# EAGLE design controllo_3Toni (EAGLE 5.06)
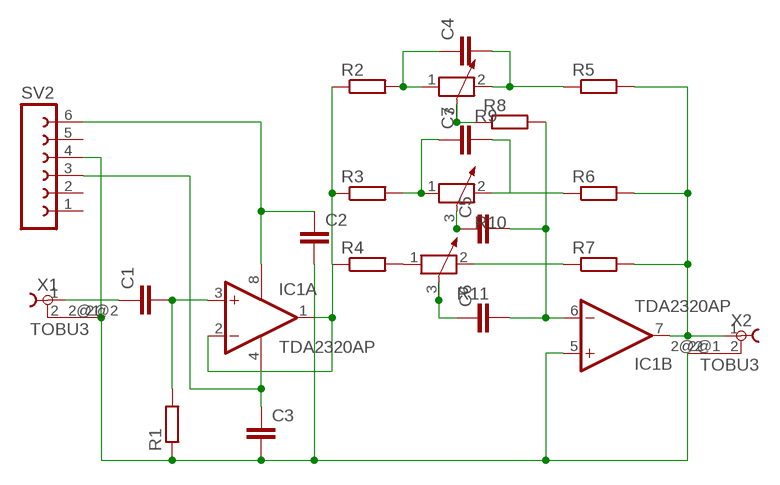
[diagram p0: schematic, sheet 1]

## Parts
C1  C-EU050-025X075  [C050-025X075]
C2  C-EU050-025X075  [C050-025X075]
C3  C-EU050-025X075  [C050-025X075]
C4  C-EU050-025X075  [C050-025X075]
C5  C-EU050-025X075  [C050-025X075]
C6  C-EU050-025X075  [C050-025X075]
C7  C-EU050-025X075  [C050-025X075]
IC1  TDA2320AP  [DIL08]
R1  R-EU_0207/10  [0207/10]
R2  R-EU_0207/10  [0207/10]
R3  R-EU_0207/10  [0207/10]
R4  R-EU_0207/10  [0207/10]
R5  R-EU_0207/10  [0207/10]
R6  R-EU_0207/10  [0207/10]
R7  R-EU_0207/10  [0207/10]
R8  R-EU_0207/10  [0207/10]
R9  POTENTIOMETER_PT-10S  [PT-10S]
R10  POTENTIOMETER_PT-10S  [PT-10S]
R11  POTENTIOMETER_PT-10S  [PT-10S]
SV2  FE06-1  [FE06]
X1  TOBU3  [TOBU3]
X2  TOBU3  [TOBU3]

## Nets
N$1: IC1.1(A:OUT) IC1.2(A:-IN) R2.1 R3.1 R4.1
N$2: C4.2 R5.1 R9.2
N$3: C7.2 R6.1 R10.2
N$4: R7.1 R11.2
N$5: C5.1 R10.3
N$6: C6.1 R11.3
N$7: C2.1 IC1.8(P:V+) SV2.6
N$8: C4.1 R2.2 R9.1
N$9: R8.1 R9.3
N$10: C5.2 C6.2 IC1.6(B:-IN) R8.2
N$11: IC1.7(B:OUT) R5.2 R6.2 R7.2 X2.1
N$12: C1.2 IC1.3(A:+IN) R1.2
N$13: C1.1 X1.1
N$14: C3.1 IC1.4(P:V-) SV2.3
N$15: C2.2 C3.2 IC1.5(B:+IN) R1.1 SV2.4 X1.2@2 X2.2@2
N$16: R4.2 R11.1
N$17: C7.1 R3.2 R10.1
Unconnected: SV2.1 SV2.2 SV2.5 X1.2 X1.2@1 X2.2 X2.2@1

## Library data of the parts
C1-C7 = resistor:C-EU: CAPACITOR, European symbol
IC1 = linear:TDA2320A: Power OP AMP
R1-R8 = resistor:R-EU_: RESISTOR, European symbol
R9-R11 = rcl:POTENTIOMETER_: Potentiometer
SV2 = con-lsta:FE06-1: FEMALE HEADER
X1 X2 = con-hirschmann:TOBU3: Female Cinch CONNECTOR ( RCA Jack )

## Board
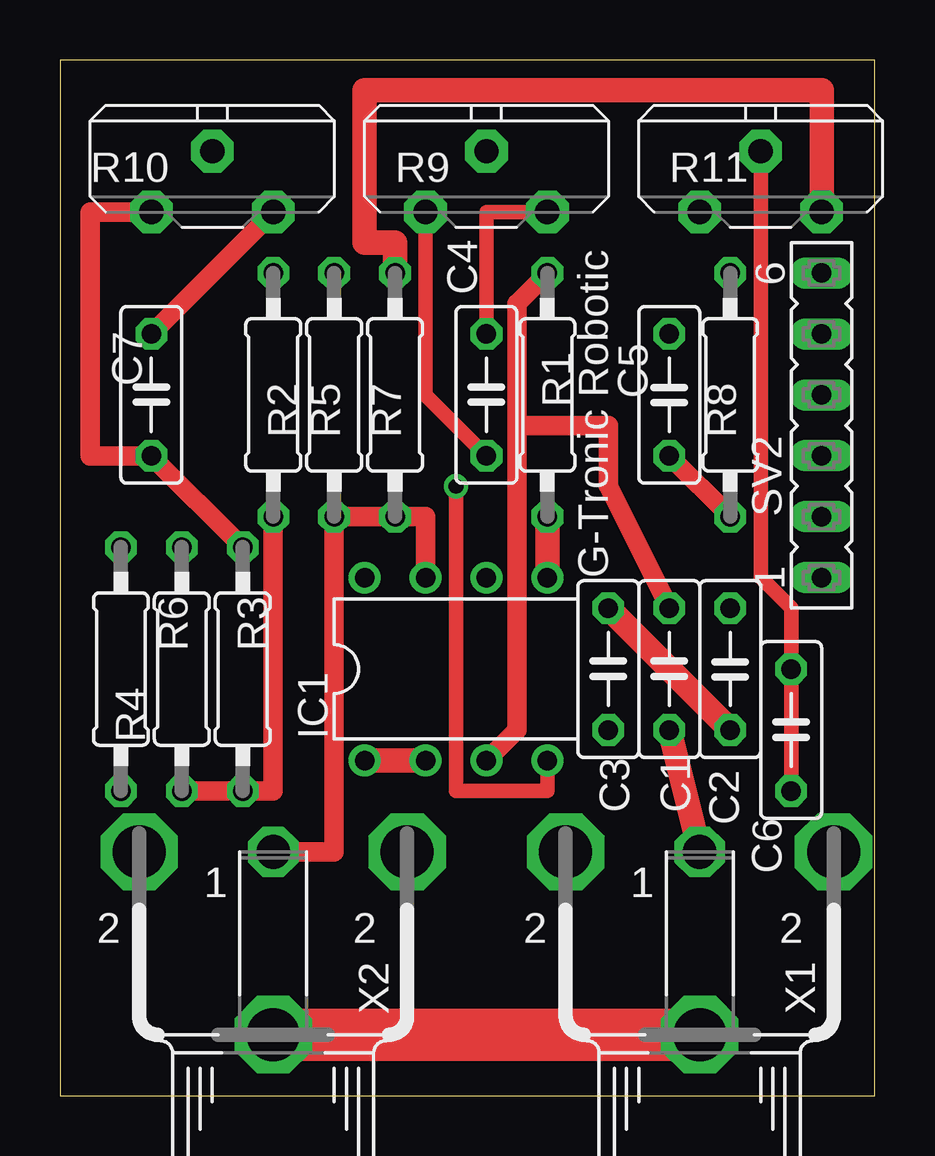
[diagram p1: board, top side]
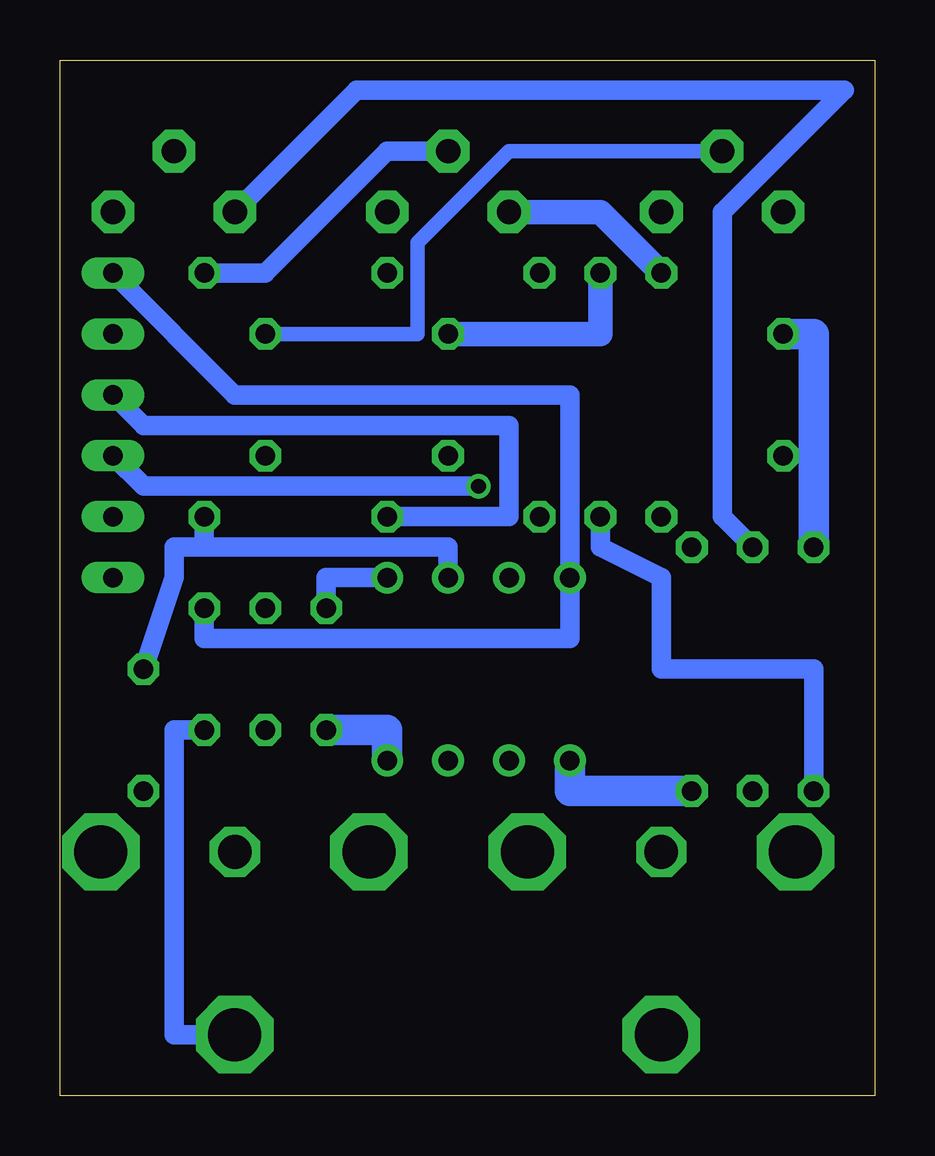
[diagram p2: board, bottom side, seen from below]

Size 33.96 x 43.17 mm. Coordinates in mm from the lower left corner, seen from the top.
Outline: 0,0 33.96,0 33.96,43.17 0,43.17 0,0
Copper layers (1*16): Top 0.035mm / dielectric 1.5mm / Bottom 0.035mm
Design rules "default": minimum track width 10mil, minimum drill 24mil, track to track 8mil, track to pad 8mil, pad to pad 8mil, via to via 8mil, smd to smd 8mil, copper to edge 40mil, drill to drill 8mil, minimum pad ring 10mil, minimum via ring 8mil, stop-mask expansion 4mil, vias tented up to drill 0mil, thermal gap 10mil

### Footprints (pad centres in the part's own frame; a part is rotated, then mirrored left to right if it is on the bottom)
C050-025X075 = drill 0.813 octagon: 1 -2.54,0; 2 2.54,0
DIL08 = drill 0.813 pad 1.27 round: 1 -3.81,-3.81; 2 -1.27,-3.81; 3 1.27,-3.81; 4 3.81,-3.81; 5 3.81,3.81; 6 1.27,3.81; 7 -1.27,3.81; 8 -3.81,3.81
0207/10 = drill 0.813 octagon: 1 -5.08,0; 2 5.08,0
PT-10S = drill 1.016 pad 1.778 octagon: 1 -2.54,-1.27; 2 2.54,-1.27; 3 0,1.27
FE06 = drill 0.813 long: 1 -6.35,0; 2 -3.81,0; 3 -1.27,0; 4 1.27,0; 5 3.81,0; 6 6.35,0
TOBU3 = drill 1.397 octagon: 1 0,-2.54 | drill 2.21 octagon: 2 5.588,-2.54; 2@1 -5.588,-2.54; 2@2 0,5.08

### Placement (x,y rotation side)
C1  25.4,17.78 90 top
C2  27.94,17.78 270 top
C3  22.86,17.78 90 top
C4  17.78,29.21 90 top
C5  25.4,29.21 270 top
C6  30.48,15.24 90 top
C7  3.81,29.21 90 top
IC1  16.51,17.78 0 top
R1  20.32,29.21 90 top
R2  8.89,29.21 90 top
R3  7.62,17.78 90 top
R4  5.08,17.78 90 top
R5  11.43,29.21 270 top
R6  2.54,17.78 270 top
R7  13.97,29.21 270 top
R8  27.94,29.21 270 top
R9  17.78,38.1 0 top
R10  6.35,38.1 0 top
R11  29.21,38.1 0 top
SV2  31.75,27.94 90 top
X1  26.67,7.62 180 top
X2  8.89,7.62 180 top

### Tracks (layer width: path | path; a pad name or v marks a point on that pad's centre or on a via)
N$1
  Top 0.813: R4.1 R3.1 8.89,12.7 R2.1
  Top 1.016: IC1.1 IC1.2
  Bottom 1.27: IC1.1 12.7,12.7 R3.1
N$2
  Top 0.61: R9.2 17.78,36.83 C4.2
  Bottom 1.016: R5.1 11.43,31.75 C4.2
N$3
  Top 0.813: C7.2 R10.2
  Bottom 1.27: R6.1 2.54,31.75 C7.2
N$4
  Top 1.016: R7.1 13.97,35.56 12.7,35.56 12.7,41.91 31.75,41.91 R11.2
N$5
  Bottom 0.61: C5.1 22.86,31.75 19.05,31.75 19.05,35.56 15.24,39.37 R10.3
N$6
  Top 0.61: C6.1 30.48,20.32 29.21,21.59 R11.3
N$7
  Bottom 0.813: C2.1 27.94,19.05 12.7,19.05 IC1.8 12.7,29.21 26.67,29.21 SV2.6
N$8
  Top 0.61: C4.1 15.24,29.21 R9.1
  Bottom 1.016: R2.2 11.43,36.83 R9.1
N$9
  Bottom 0.813: R8.1 25.4,34.29 20.32,39.37 R9.3
N$10
  Top 0.813: R8.2 C5.2
  Bottom 0.813: IC1.6 17.78,22.86 27.94,22.86 | 27.94,22.86 R8.2 | 27.94,22.86 29.21,22.86 29.21,21.59 C6.2
N$11
  Top 0.813: IC1.7 15.24,24.13 R7.2 R5.2 11.43,10.16 X2.1
  Bottom 0.813: R6.2 2.54,17.78 8.89,17.78 8.89,21.59 11.43,22.86 R5.2
N$12
  Top 0.813: IC1.3 19.05,15.24 19.05,27.94 | 19.05,27.94 19.05,33.02 R1.2 | 19.05,27.94 22.86,27.94 22.86,25.4 C1.2
N$13
  Top 1.016: X1.1 C1.1
N$14  (via drill 0.61)
  Top 0.61: v16.51,25.4 16.51,12.7 20.32,12.7 IC1.4
  Bottom 0.813: SV2.3 30.48,25.4 v16.51,25.4
  Bottom 1.27: IC1.4 20.32,15.24 C3.1
N$15
  Top 1.016: IC1.5 R1.1 | C2.2 C3.2
  Top 2.184: X2.2@2 X1.2@2
  Bottom 0.813: C3.2 22.86,21.59 IC1.5 | C2.2 29.21,15.24 29.21,2.54 X1.2@2 | SV2.4 30.48,27.94 15.24,27.94 15.24,24.13 R1.1
N$16
  Bottom 0.813: R4.2 6.35,24.13 6.35,36.83 1.27,41.91 21.59,41.91 R11.1
N$17
  Top 0.813: R3.2 C7.1 1.27,26.67 1.27,36.83 R10.1

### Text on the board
tNames: G-Tronic Robotic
